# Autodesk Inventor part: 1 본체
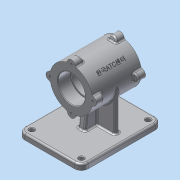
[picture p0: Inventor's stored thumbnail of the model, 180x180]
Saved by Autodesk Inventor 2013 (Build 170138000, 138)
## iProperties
Created: 2015-12
Part Number: 1 본체
Material: 알루미늄 6061
Document SubType Name: Modeling
Designer: Administrator
Density: 2.71 g/cm^3
Mass: 1165.53 g
Surface Area: 815.605 cm^2
Volume: 430.084 cm^3
Author: Administrator
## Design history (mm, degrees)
node "작업 평면2"
sketch "스케치16"
  geometry: C1 r 7 at (0, 37); C2 r 7 at (0, -37); C3 r 7 at (-37, 0); C4 r 7 at (37, 0); A1 r 37 centre (0, 0) between (0, 37) and (-37, 0); 1 further point
  constraints: 5 centre point, 4 point on circle, 3 equal radius, 2 horizontal alignment, 2 vertical alignment, 1 coincident
  dimensions: "d96" = 74 diameter of A1; "d98" = 14 diameter of C1
extrude "돌출6" new body sketch "스케치16" distance "d99" = 15; taper "d100" = 0 deg
sketch "스케치26"
  geometry: L1 (-27.5, 30)-(-42.5, 30) reference; L2 (-42.5, 30)-(-42.5, 44) reference; L3 (-42.5, 44)-(-27.5, 44) reference; L4 (-27.5, 44)-(-27.5, 30) reference; L5 (-27.5, -44)-(-42.5, -44) reference; L6 (-42.5, -44)-(-42.5, -30) reference; L7 (-42.5, -30)-(-27.5, -30) reference; L8 (-27.5, -30)-(-27.5, -44) reference; L9 (-31.388, 47.681)-(-27.5, 37); L10 (0, 47.681)-(-31.388, 47.681); L11 (-27.5, 0)-(0, 0); L12 (-27.5, 0)-(-27.5, 37); L13 (0, 0)-(0, 47.681)
  constraints: 11 end point, 1 collinear, 1 midpoint, 1 parallel
  dimensions: "d169" = 110 deg angle of L3 L9; "d171" = 95.36221 diameter of L10 L11; "d173" = 27.5 distance of L11.start L11.end
revolve "회전5" sketch "스케치26" stored, may be unused: angle "d174" = 90 deg
sketch "스케치25"
  geometry: C1 r 37 at (0, -37); 1 further point
  constraints: 1 centre point, 1 coincident
  dimensions: "d121" = 74 diameter of C1
extrude "돌출11" join sketch "스케치25" distance "d123" = 85; taper "d124" = 0 deg
hole "구멍4" diameter "d136" = 3.242; stored, may be unused: countersink angle "d140" = 82 deg, drill point angle "d142" = 118 deg; dims "d134" = 10, "d135" = 10, "d137" = 9, "d138" = 3.023, "d139" = 2, "d141" = 11
hole "구멍5" diameter "d145" = 42; stored, may be unused: countersink angle "d149" = 82 deg, drill point angle "d151" = 118 deg; dims "d143" = 10, "d144" = 10, "d146" = 9, "d147" = 47, "d148" = 22, "d150" = 11
hole "구멍6" diameter "d154" = 47; stored, may be unused: countersink angle "d158" = 82 deg, drill point angle "d160" = 0 deg; dims "d152" = 10, "d153" = 10, "d155" = 9, "d156" = 47, "d157" = 22, "d159" = 22
fillet "모깎기1" dims "d164" = 0.3
chamfer "모따기1" distance "d165" = 1; stored, may be unused: second distance "d166" = 2, angle "d167" = 45 deg
fillet "모깎기2" dims "d182" = 3
node "작업 평면4"
sketch "스케치30"
  geometry: L1 (48, -55)-(-68, -55); L2 (-80, -43)-(-80, 43); L3 (-68, 55)-(48, 55); L4 (60, 43)-(60, -43); C1 r 4 at (-68, 43); C2 r 4 at (-68, -43); C3 r 4 at (48, -43); C4 r 4 at (48, 43); A1 r 12 centre (-68, 43) between (-68, 55) and (-80, 43); A2 r 12 centre (-68, -43) between (-80, -43) and (-68, -55); A3 r 12 centre (48, -43) between (48, -55) and (60, -43); A4 r 12 centre (48, 43) between (60, 43) and (48, 55); 7 further points
  constraints: 8 centre point, 8 end point, 8 point on circle, 8 tangent, 6 equal radius, 6 point on line, 4 concentric, 2 parallel, 1 coincident, 1 horizontal, 1 horizontal alignment, 1 midpoint, 1 perpendicular
  dimensions: "d186" = 80 distance from line of point (0, 0) L2; "d187" = 140 distance of point (-80, 55) point (60, 55); "d188" = 110 distance of point (60, 55) point (60, -55); "d189" = 8 diameter of C1; "d190" = 12 radius of A1
extrude "돌출13" join sketch "스케치30" distance "d191" = 10; taper "d192" = 0 deg
sketch "스케치31"
  geometry: L1 (4, -37)-(-4, -37); L2 (-4, -37)-(-4, 37); L3 (-4, 37)-(4, 37); L4 (4, 37)-(4, -37); L5 (4, -37)-(-4, 37); L6 (-4, -37)-(4, 37); 1 further point
  constraints: 12 end point, 2 midpoint, 2 parallel, 1 horizontal, 1 perpendicular
  dimensions: "d193" = 8 distance of L2.end L3.end; "d195" = 74 distance of L3.end L1.start
extrude "돌출14" join sketch "스케치31" stored distance "d196" = 10; taper "d197" = 0 deg
sketch "스케치32"
  geometry: L1 (30.526, -37)-(31.5, -38.621) reference; L2 (31.5, -38.621)-(42.5, -38.621) reference; L3 (42.5, -38.621)-(42.5, -44) reference; L4 (42.5, -44)-(32.148, -44) reference; L5 (29.329, -42.026)-(27.5, -37) reference; L6 (27.5, -37)-(4, -37) reference; L7 (4, -37)-(4, -70) reference; L8 (4, -70)-(80, -70) reference; L9 (80, -70)-(80, -80) reference; L10 (80, -80)-(-60, -80) reference; L11 (-60, -80)-(-60, -70) reference; L12 (-60, -70)-(-4, -70) reference; L13 (-4, -70)-(-4, -37) reference; L14 (-4, -37)-(-27.5, -37) reference; L15 (-27.5, -37)-(-29.329, -42.026) reference; L16 (-32.148, -44)-(-42.5, -44) reference; L17 (-42.5, -44)-(-42.5, -38.621) reference; L18 (-42.5, -38.621)-(-31.5, -38.621) reference; L19 (-31.5, -38.621)-(-30.526, -37) reference; L20 (-30.526, -37)-(-31.5, -35.379) reference; L21 (-31.5, -35.379)-(-42.5, -35.379) reference; L22 (-42.5, -35.379)-(-42.5, -24.5) reference; L23 (-42.5, -24.5)-(-41.5, -23.5) reference; L24 (-41.5, -23.5)-(-20.8, -23.5) reference; L25 (-20.5, -23.2)-(-20.5, -21) reference; L26 (-20.5, -21)-(20.5, -21) reference; L27 (20.5, -21)-(20.5, -23.2) reference; L28 (20.8, -23.5)-(41.5, -23.5) reference; L29 (41.5, -23.5)-(42.5, -24.5) reference; L30 (42.5, -24.5)-(42.5, -35.379) reference; L31 (42.5, -35.379)-(31.5, -35.379) reference; L32 (31.5, -35.379)-(30.526, -37) reference; L33 (31.5, 38.621)-(30.526, 37) reference; L34 (30.526, 37)-(31.5, 35.379) reference; L35 (31.5, 35.379)-(42.5, 35.379) reference; L36 (42.5, 35.379)-(42.5, 24.5) reference; L37 (42.5, 24.5)-(41.5, 23.5) reference; L38 (41.5, 23.5)-(20.8, 23.5) reference; L39 (20.5, 23.2)-(20.5, 21) reference; L40 (20.5, 21)-(-20.5, 21) reference; L41 (-20.5, 21)-(-20.5, 23.2) reference; L42 (-20.8, 23.5)-(-41.5, 23.5) reference; L43 (-41.5, 23.5)-(-42.5, 24.5) reference; L44 (-42.5, 24.5)-(-42.5, 35.379) reference; L45 (-42.5, 35.379)-(-31.5, 35.379) reference; L46 (-31.5, 35.379)-(-30.526, 37) reference; L47 (-30.526, 37)-(-31.5, 38.621) reference; L48 (-31.5, 38.621)-(-42.5, 38.621) reference; L49 (-42.5, 38.621)-(-42.5, 44) reference; L50 (-42.5, 44)-(-32.148, 44) reference; L51 (-29.329, 42.026)-(-27.5, 37) reference; L52 (-27.5, 37)-(27.5, 37) reference; L53 (27.5, 37)-(29.329, 42.026) reference; L54 (32.148, 44)-(42.5, 44) reference; L55 (42.5, 44)-(42.5, 38.621) reference; L56 (42.5, 38.621)-(31.5, 38.621) reference; L57 (-19.665, -26.546)-(-25, -70); L58 (19.663, -26.534)-(25, -70); L59 (16.716, -26.546)-(-19.665, -26.546); A1 r 0.3 centre (-20.8, -23.2) between (-20.8, -23.5) and (-20.5, -23.2) reference; A2 r 0.3 centre (20.8, -23.2) between (20.5, -23.2) and (20.8, -23.5) reference; A3 r 0.3 centre (20.8, 23.2) between (20.8, 23.5) and (20.5, 23.2) reference; A4 r 0.3 centre (-20.8, 23.2) between (-20.5, 23.2) and (-20.8, 23.5) reference; A5 r 12.499 centre (18.14, -14.128) between (16.716, -26.546) and (19.663, -26.534); 1 further point
  constraints: 6 end point, 3 point on line, 2 point on circle, 1 centre point, 1 parallel, 4 other
  dimensions: "d198" = 50 distance of L57.end L58.end; "d200" = 25 horizontal distance of L57.end point (0, 0); "d201" = 97 deg angle of L8 L58; "d202" = 97 deg angle of L12 L57 (= d201)
extrude "돌출15" join sketch "스케치32" stored distance "d203" = 12; taper "d204" = 0 deg
sketch "스케치33"
  geometry: L1 (-70, -55)-(-80, -55) reference; L2 (-80, -55)-(-80, 55) reference; L3 (-80, 55)-(-70, 55) reference; L4 (-70, 55)-(-70, 37) reference; L5 (-70, 37)-(0, 37) reference; L6 (0, -37)-(-70, -37) reference; L7 (-70, -37)-(-70, -55) reference; C1 r 21 at (0, 0) reference; A1 r 37 centre (0, 0) between (0, -37) and (0, 37) reference; 3 further points
  constraints: 1 coincident, 1 point on circle
  dimensions: "d205" = 45 deg dimension on point (0, 0) point (26.163, -26.163) point (0, -37)
  node "절단 모서리 투영19"
node "작업 평면5"
sketch "스케치34"
  geometry: L1 (-26.057, 8.89)-(26.057, 8.89); L2 (26.057, 8.89)-(26.057, -8.89); L3 (26.057, -8.89)-(-26.057, -8.89); L4 (-26.057, -8.89)-(-26.057, 8.89); 4 further points
  constraints: 2 midpoint, 1 coincident, 1 horizontal alignment, 1 vertical, 1 vertical alignment, 2 other
  dimensions: "d206" = 52.11428 distance between parallel lines of L2 L4; "d207" = 17.78017 distance between parallel lines of L3 L1
feature "엠보싱2" sketch "스케치34" dims "d143" = 10, "d144" = 10, "d208" = 0.5, "d209" = 0
fillet "모깎기5" dims "d210" = 3
fillet "모깎기6" dims "d211" = 3
fillet "모깎기7" dims "d212" = 3
chamfer "모따기2" distance "d213" = 1; stored, may be unused: second distance "d214" = 2, angle "d215" = 45 deg
node "솔리드1"
mirror "대칭1"
pattern_circular "원형 패턴3" dims angle "d162" = 360 deg
mirror "대칭2"
node "솔리드3"
node "절단 모서리 투영15"
node "절단 모서리 투영18"
other parameters: "d95" = 42.5
